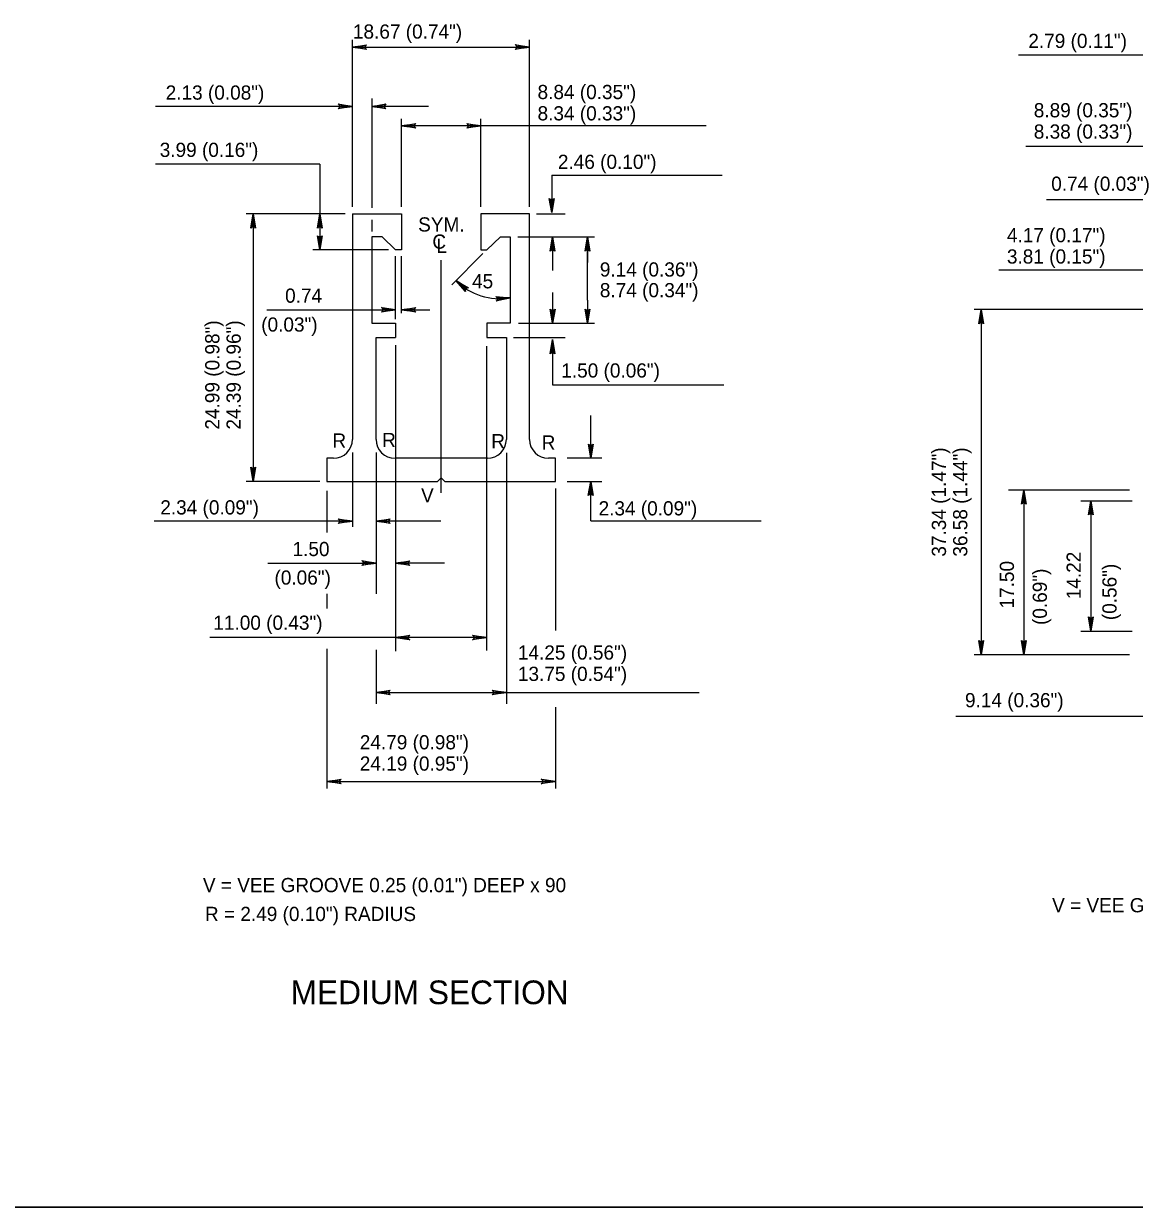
# Model space of a CAD drawing. Extents: x 650495 to 651400, y 297864 to 299646.
# Drawn here: x 650729.8 to 650964.3, y 299066.6 to 299316.5 of the extents above; entities that cross this region are included whole.
import ezdxf

# ---------------------------------------------------------------- set-up
doc = ezdxf.new("R2010")
doc.units = 0
for name, color, linetype in [('1', 7, 'Continuous'), ('2', 7, 'Continuous'), ('3', 7, 'Continuous')]:
    doc.layers.add(name, color=color, linetype=linetype)

# ---------------------------------------------------------------- blocks, each defined once
blk = doc.blocks.new('RARROW')
at = {"layer": '3'}
blk.add_lwpolyline([(-2.2695, 0.285), (-2.184875, 0.12075), (0, 0), (-2.2695, 0.285), (-2.38575, 0.384625), (0, 0), (-2.183125, -0.108), (-2.262875, -0.2705), (0, 0), (-2.38575, -0.379125), (-2.262875, -0.2705)], dxfattribs=at)

msp = doc.modelspace()

# ---------------------------------------------------------------- linework, layer by layer
at = {"layer": '1'}
for p, q in [((651321.31, 299066.63), (650535.31, 299066.63)), ((650535.31, 299066.63), (651121.31, 299066.63))]:
    msp.add_line(p, q, dxfattribs=at)
at = {"layer": '2'}
for p, q in [((650799.19, 299277.85), (650799.19, 299313.05)), ((650799.19, 299311.55), (650836.57, 299311.55)), ((650836.57, 299277.85), (650836.57, 299313.05)), ((650939.78, 299309.88), (650981.53, 299309.88)), ((650799.19, 299299.03), (650757.59, 299299.03)), ((650803.27, 299300.72), (650803.27, 299277.64)), ((650815.23, 299299.03), (650803.27, 299299.03)), ((650809.57, 299277.85), (650809.57, 299296.41)), ((650826.32, 299277.85), (650826.32, 299296.41)), ((650873.9, 299294.91), (650809.57, 299294.91)), ((650941.38, 299290.65), (651010.66, 299290.65)), ((650792.32, 299286.85), (650757.61, 299286.85)), ((650792.32, 299286.85), (650792.32, 299268.73)), ((650841.26, 299284.47), (650841.26, 299276.59)), ((650841.26, 299284.47), (650877.26, 299284.47)), ((650945.72, 299279.38), (650990.57, 299279.38)), ((650797.69, 299276.35), (650776.74, 299276.35)), ((650778.24, 299276.35), (650778.24, 299219.85)), ((650797.69, 299276.35), (650790.82, 299276.35)), ((650799.19, 299276.35), (650809.57, 299276.35)), ((650799.19, 299276.35), (650799.19, 299228.73)), ((650809.57, 299276.35), (650809.57, 299268.73)), ((650809.57, 299276.35), (650809.57, 299276.35)), ((650836.57, 299276.35), (650826.32, 299276.35)), ((650826.32, 299276.35), (650826.32, 299268.73)), ((650826.32, 299276.35), (650826.32, 299276.35)), ((650836.57, 299228.73), (650836.57, 299276.35)), ((650838.07, 299276.35), (650844.13, 299276.35)), ((650803.27, 299275.07), (650803.27, 299272.64)), ((650805.44, 299271.48), (650803.27, 299271.48)), ((650803.27, 299271.48), (650803.27, 299253.23)), ((650805.44, 299271.48), (650808.32, 299268.73)), ((650830.44, 299271.48), (650827.57, 299268.73)), ((650830.44, 299271.48), (650832.49, 299271.48)), ((650832.49, 299271.48), (650832.49, 299253.23)), ((650834.15, 299271.48), (650850.3, 299271.48)), ((650841.46, 299271.48), (650841.46, 299264.4)), ((650848.8, 299258.1), (650848.8, 299271.48)), ((650848.8, 299271.48), (650848.8, 299266.1)), ((650806.82, 299268.73), (650790.82, 299268.73)), ((650809.57, 299268.73), (650808.32, 299268.73)), ((650826.32, 299268.73), (650827.57, 299268.73)), ((650808.32, 299254.13), (650808.32, 299267.43)), ((650809.57, 299255.35), (650809.57, 299267.43)), ((650817.94, 299217.44), (650817.94, 299266.58)), ((650826.74, 299267.94), (650820.15, 299261.36)), ((650935.67, 299264.51), (650971.55, 299264.51)), ((650841.46, 299259.75), (650841.46, 299253.23)), ((650781.14, 299256.1), (650808.32, 299256.1)), ((650809.57, 299256.1), (650815.56, 299256.1)), ((650848.8, 299258.1), (650848.8, 299253.23)), ((650980.03, 299256.15), (650930.42, 299256.15)), ((650931.92, 299256.15), (650931.92, 299183.27)), ((650803.27, 299253.23), (650808.32, 299253.23)), ((650808.32, 299253.23), (650808.32, 299250.23)), ((650832.49, 299253.23), (650827.57, 299253.23)), ((650827.57, 299253.23), (650827.57, 299250.23)), ((650834.26, 299253.23), (650850.3, 299253.23)), ((650850.3, 299253.23), (650850.3, 299253.23)), ((650804.19, 299228.73), (650804.19, 299250.23)), ((650804.19, 299250.23), (650808.32, 299250.23)), ((650808.32, 299248.62), (650808.32, 299184.06)), ((650827.57, 299250.23), (650831.69, 299250.23)), ((650831.69, 299250.23), (650831.69, 299228.73)), ((650833.19, 299250.23), (650844.13, 299250.23)), ((650841.44, 299249.8), (650841.44, 299240.21)), ((650827.57, 299184.15), (650827.57, 299248.44)), ((650841.44, 299240.21), (650877.62, 299240.21)), ((650849.5, 299224.73), (650849.5, 299233.78)), ((650799.19, 299225.98), (650799.19, 299210.25)), ((650804.19, 299225.98), (650804.19, 299196.16)), ((650795.19, 299224.73), (650793.82, 299224.73)), ((650793.82, 299224.73), (650793.82, 299219.85)), ((650827.69, 299224.73), (650808.19, 299224.73)), ((650831.69, 299225.88), (650831.69, 299172.88)), ((650842.07, 299224.73), (650840.57, 299224.73)), ((650842.07, 299219.85), (650842.07, 299224.73)), ((650851.84, 299224.73), (650844.54, 299224.73)), ((650792.32, 299219.85), (650776.74, 299219.85)), ((650793.82, 299219.85), (650817.19, 299219.85)), ((650818.69, 299219.85), (650842.07, 299219.85)), ((650844.54, 299219.85), (650851.84, 299219.85)), ((650849.5, 299211.53), (650849.5, 299219.85)), ((650793.82, 299217.85), (650793.82, 299209.1)), ((650842.07, 299218.35), (650842.07, 299188.38)), ((650963.28, 299218.03), (650937.68, 299218.03)), ((650940.92, 299218.03), (650940.92, 299183.27)), ((650952.95, 299215.77), (650963.78, 299215.77)), ((650955.1, 299215.77), (650955.1, 299188.27)), ((650799.19, 299211.48), (650757.31, 299211.48)), ((650817.87, 299211.48), (650804.19, 299211.48)), ((650849.5, 299211.53), (650885.5, 299211.53)), ((650781.32, 299202.63), (650804.19, 299202.63)), ((650818.6, 299202.63), (650808.32, 299202.63)), ((650793.82, 299196.14), (650793.82, 299193.02)), ((650827.57, 299186.89), (650769.12, 299186.89)), ((650952.95, 299188.27), (650963.78, 299188.27)), ((650793.82, 299184.55), (650793.82, 299155.03)), ((650804.19, 299184.3), (650804.19, 299172.88)), ((650963.28, 299183.27), (650930.42, 299183.27)), ((650963.28, 299183.27), (650934.04, 299183.27)), ((650804.19, 299175.3), (650872.37, 299175.3)), ((650842.07, 299172.18), (650842.07, 299155.03)), ((650926.56, 299170.3), (650983.03, 299170.3)), ((650793.82, 299156.53), (650842.07, 299156.53))]:
    msp.add_line(p, q, dxfattribs=at)
msp.add_lwpolyline([(650817.19, 299219.85), (650817.94, 299220.6), (650818.69, 299219.85)], dxfattribs=at)
for centre, radius, start, end in [((650830.27, 299271.48), 13.06, 225.0095, 279.8021), ((650795.19, 299228.73), 4, 270, 0), ((650808.19, 299228.73), 4, 180, 270), ((650827.69, 299228.73), 4, 270, 0), ((650840.57, 299228.73), 4, 180, 270)]:
    msp.add_arc(centre, radius, start, end, dxfattribs=at)

# ---------------------------------------------------------------- block references
at = {"layer": '2', "xscale": 1.2574347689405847}
for p, yscale, rotation in [((650799.19, 299311.55), 1.3092961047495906, 180), ((650803.27, 299299.03), 1.3092961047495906, 180), ((650809.57, 299294.91), 1.3092961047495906, 180), ((650841.26, 299276.59), 1.3092961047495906, -90.00000000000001), ((650778.24, 299276.35), 1.3092961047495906, 89.99999999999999), ((650792.32, 299276.35), 1.3092961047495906, 89.99999999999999), ((650792.32, 299268.73), 1.3092961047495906, -90.00000000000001), ((650841.46, 299271.48), 1.3092961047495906, 89.99999999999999), ((650848.8, 299271.48), 1.3092961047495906, 89.99999999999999), ((650821.04, 299262.24), 1.3092961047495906, 140.9194989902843), ((650832.49, 299258.61), 1.3092961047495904, 4.175089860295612), ((650809.57, 299256.1), 1.3092961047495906, 180), ((650841.46, 299253.23), 1.3092961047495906, -90.00000000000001), ((650848.8, 299253.23), 1.3092961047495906, -90.00000000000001), ((650931.92, 299256.15), 1.3092961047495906, 89.99999999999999), ((650841.44, 299249.8), 1.3092961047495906, 89.99999999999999), ((650849.5, 299224.73), 1.3092961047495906, -90.00000000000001), ((650778.24, 299219.85), 1.3092961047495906, -90.00000000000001), ((650849.5, 299219.85), 1.3092961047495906, 89.99999999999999), ((650940.92, 299218.03), 1.3092961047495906, 89.99999999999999), ((650955.1, 299215.77), 1.3092961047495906, 89.99999999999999), ((650804.19, 299211.48), 1.3092961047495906, 180), ((650808.32, 299202.63), 1.3092961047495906, 180), ((650955.1, 299188.27), 1.3092961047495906, -90.00000000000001), ((650808.32, 299186.89), 1.3092961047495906, 180), ((650931.92, 299183.27), 1.3092961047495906, -90.00000000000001), ((650940.92, 299183.27), 1.3092961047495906, -90.00000000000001), ((650804.19, 299175.3), 1.3092961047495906, 180), ((650793.82, 299156.53), 1.3092961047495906, 180)]:
    msp.add_blockref('RARROW', p, dxfattribs=dict(at, yscale=yscale, rotation=rotation))
at = {"layer": '2', "xscale": 1.2574347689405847, "yscale": 1.3092961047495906}
for p in [(650836.57, 299311.55), (650799.19, 299299.03), (650826.32, 299294.91), (650808.32, 299256.1), (650799.19, 299211.48), (650804.19, 299202.63), (650827.57, 299186.89), (650831.69, 299175.3), (650842.07, 299156.53)]:
    msp.add_blockref('RARROW', p, dxfattribs=at)

# ---------------------------------------------------------------- texts
at = {"layer": '2'}
for s, height, p in [('18.67 (0.74")', 3, (650799.3, 299313.32)), ('2.79 (0.11")', 3, (650941.89, 299311.35)), ('2.13 (0.08")', 3, (650759.77, 299300.44)), ('8.84 (0.35")', 3, (650838.28, 299300.56)), ('8.34 (0.33")', 3, (650838.28, 299296.06)), ('8.89 (0.35")', 3, (650943.04, 299296.71)), ('8.38 (0.33")', 3, (650943.04, 299292.21)), ('3.99 (0.16")', 3, (650758.51, 299288.35)), ('2.46 (0.10")', 3, (650842.57, 299285.82)), ('0.74 (0.03")', 3, (650946.72, 299281.2)), ('SYM.', 3, (650813.07, 299272.6)), ('4.17 (0.17")', 3, (650937.37, 299270.34)), ('C', 3, (650816.07, 299268.98)), ('L', 3, (650816.94, 299268.1)), ('3.81 (0.15")', 3, (650937.37, 299265.84)), ('9.14 (0.36")', 3, (650851.43, 299263.1)), ('45', 3, (650824.45, 299260.61)), ('8.74 (0.34")', 3, (650851.43, 299258.73)), ('0.74', 3, (650784.98, 299257.57)), ('(0.03")', 3, (650779.94, 299251.48)), ('1.50 (0.06")', 3, (650843.29, 299241.78)), ('R', 3, (650794.97, 299226.98)), ('R', 3, (650805.47, 299227.1)), ('R', 3, (650828.5, 299226.85)), ('R', 3, (650839.14, 299226.57)), ('2.34 (0.09")', 3, (650758.63, 299212.88)), ('V', 3, (650813.69, 299215.43)), ('2.34 (0.09")', 3, (650851.16, 299212.68)), ('1.50', 3, (650786.55, 299204.09)), ('(0.06")', 3, (650782.74, 299198.07)), ('11.00 (0.43")', 3, (650769.83, 299188.54)), ('14.25 (0.56")', 3, (650834.13, 299182.24)), ('13.75 (0.54")', 3, (650834.13, 299177.74)), ('9.14 (0.36")', 3, (650928.52, 299172.18)), ('24.79 (0.98")', 3, (650800.75, 299163.3)), ('24.19 (0.95")', 3, (650800.75, 299158.8)), ('V = VEE GROOVE 0.25 (0.01") DEEP x 90', 3, (650767.63, 299133.15)), ('V = VEE GROOVE 0.38 (0.015") DEEP x 90', 3, (650946.91, 299128.9)), ('R = 2.49 (0.10") RADIUS', 3, (650768.06, 299127.06)), ('MEDIUM SECTION', 5, (650786.15, 299109.51))]:
    msp.add_text(s, height=height, dxfattribs=at).set_placement(p)
for s, p in [('24.99 (0.98")', (650771.11, 299230.8)), ('24.39 (0.96")', (650775.61, 299230.8)), ('37.34 (1.47")', (650924.51, 299203.97)), ('36.58 (1.44")', (650929.01, 299203.97)), ('14.22 ', (650952.96, 299194.98)), ('17.50', (650938.86, 299193.03)), (' (0.69") ', (650945.81, 299188.44)), (' (0.56") ', (650960.52, 299189.46))]:
    msp.add_text(s, height=3, rotation=90, dxfattribs=at).set_placement(p)

doc.saveas('drawing.dxf')
